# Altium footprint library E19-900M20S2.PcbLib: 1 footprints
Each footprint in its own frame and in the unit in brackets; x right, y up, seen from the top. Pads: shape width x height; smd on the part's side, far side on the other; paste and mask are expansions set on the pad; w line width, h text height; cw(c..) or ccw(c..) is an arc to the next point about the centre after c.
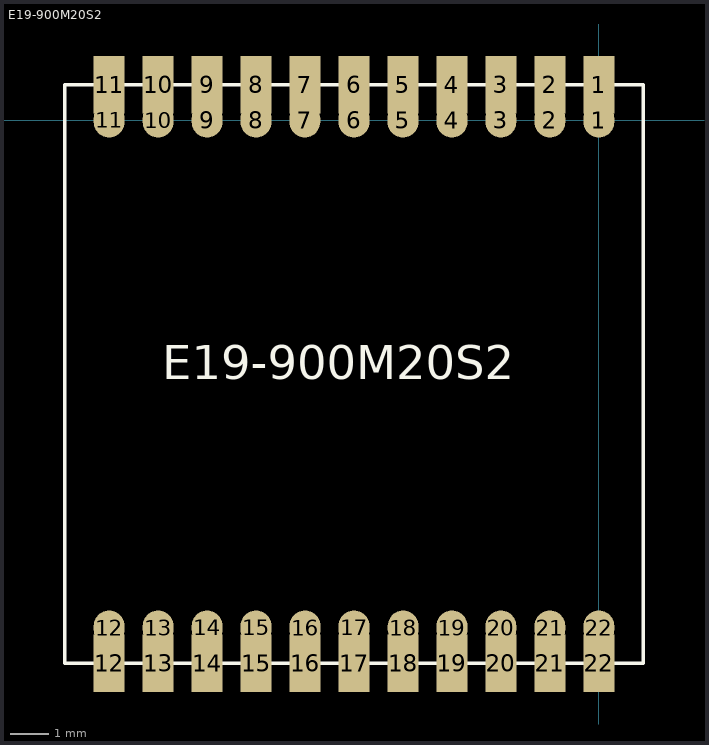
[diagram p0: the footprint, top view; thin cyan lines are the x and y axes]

## E19-900M20S2 [mm]
pads (44):
  oval 0.8x0.9 smd: 1(0,0) 2(-1.27,0) 3(-2.54,0) 4(-3.81,0) 5(-5.08,0) 6(-6.35,0) 7(-7.625,0) 8(-8.89,0) 9(-10.16,0) 10(-11.43,0) 11(-12.7,0) 12(-12.7,-13.16) 13(-11.43,-13.16) 14(-10.16,-13.16) 15(-8.89,-13.16) 16(-7.62,-13.16) 17(-6.35,-13.16) 18(-5.075,-13.16) 19(-3.81,-13.16) 20(-2.54,-13.16) 21(-1.27,-13.16) 22(0,-13.16)
  rect 0.8x1.5 smd: 1(0,0.92) 2(-1.27,0.92) 3(-2.54,0.92) 4(-3.81,0.92) 5(-5.08,0.92) 6(-6.35,0.92) 7(-7.625,0.92) 8(-8.89,0.92) 9(-10.16,0.92) 10(-11.43,0.92) 11(-12.7,0.92) 12(-12.7,-14.08) 13(-11.43,-14.08) 14(-10.16,-14.08) 15(-8.89,-14.08) 16(-7.62,-14.08) 17(-6.35,-14.08) 18(-5.075,-14.08) 19(-3.81,-14.08) 20(-2.54,-14.08) 21(-1.27,-14.08) 22(0,-14.08)
Bottom Layer:
  lines w0.25: -2.54,-13.16 -2.54,-13.04
Top Overlay:
  lines w0.1: -13.85,-14.08 1.15,-14.08 1.15,0.92 -13.85,0.92 -13.85,-14.08
  text "E19-900M20S2" at -11.326,-7.003 h1.5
